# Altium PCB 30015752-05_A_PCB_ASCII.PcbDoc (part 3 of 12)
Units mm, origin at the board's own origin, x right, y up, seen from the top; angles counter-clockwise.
Board outline 100.05 x 72 mm, 10 copper layers (Top, GND_2, Signal_3, Signal_4, PWR_5, GND_6, Signal_7, Signal_8, GND_9, Bottom), stack 1.493 mm thick; 577 components, 546 nets, 2389 pads, 1412 vias.
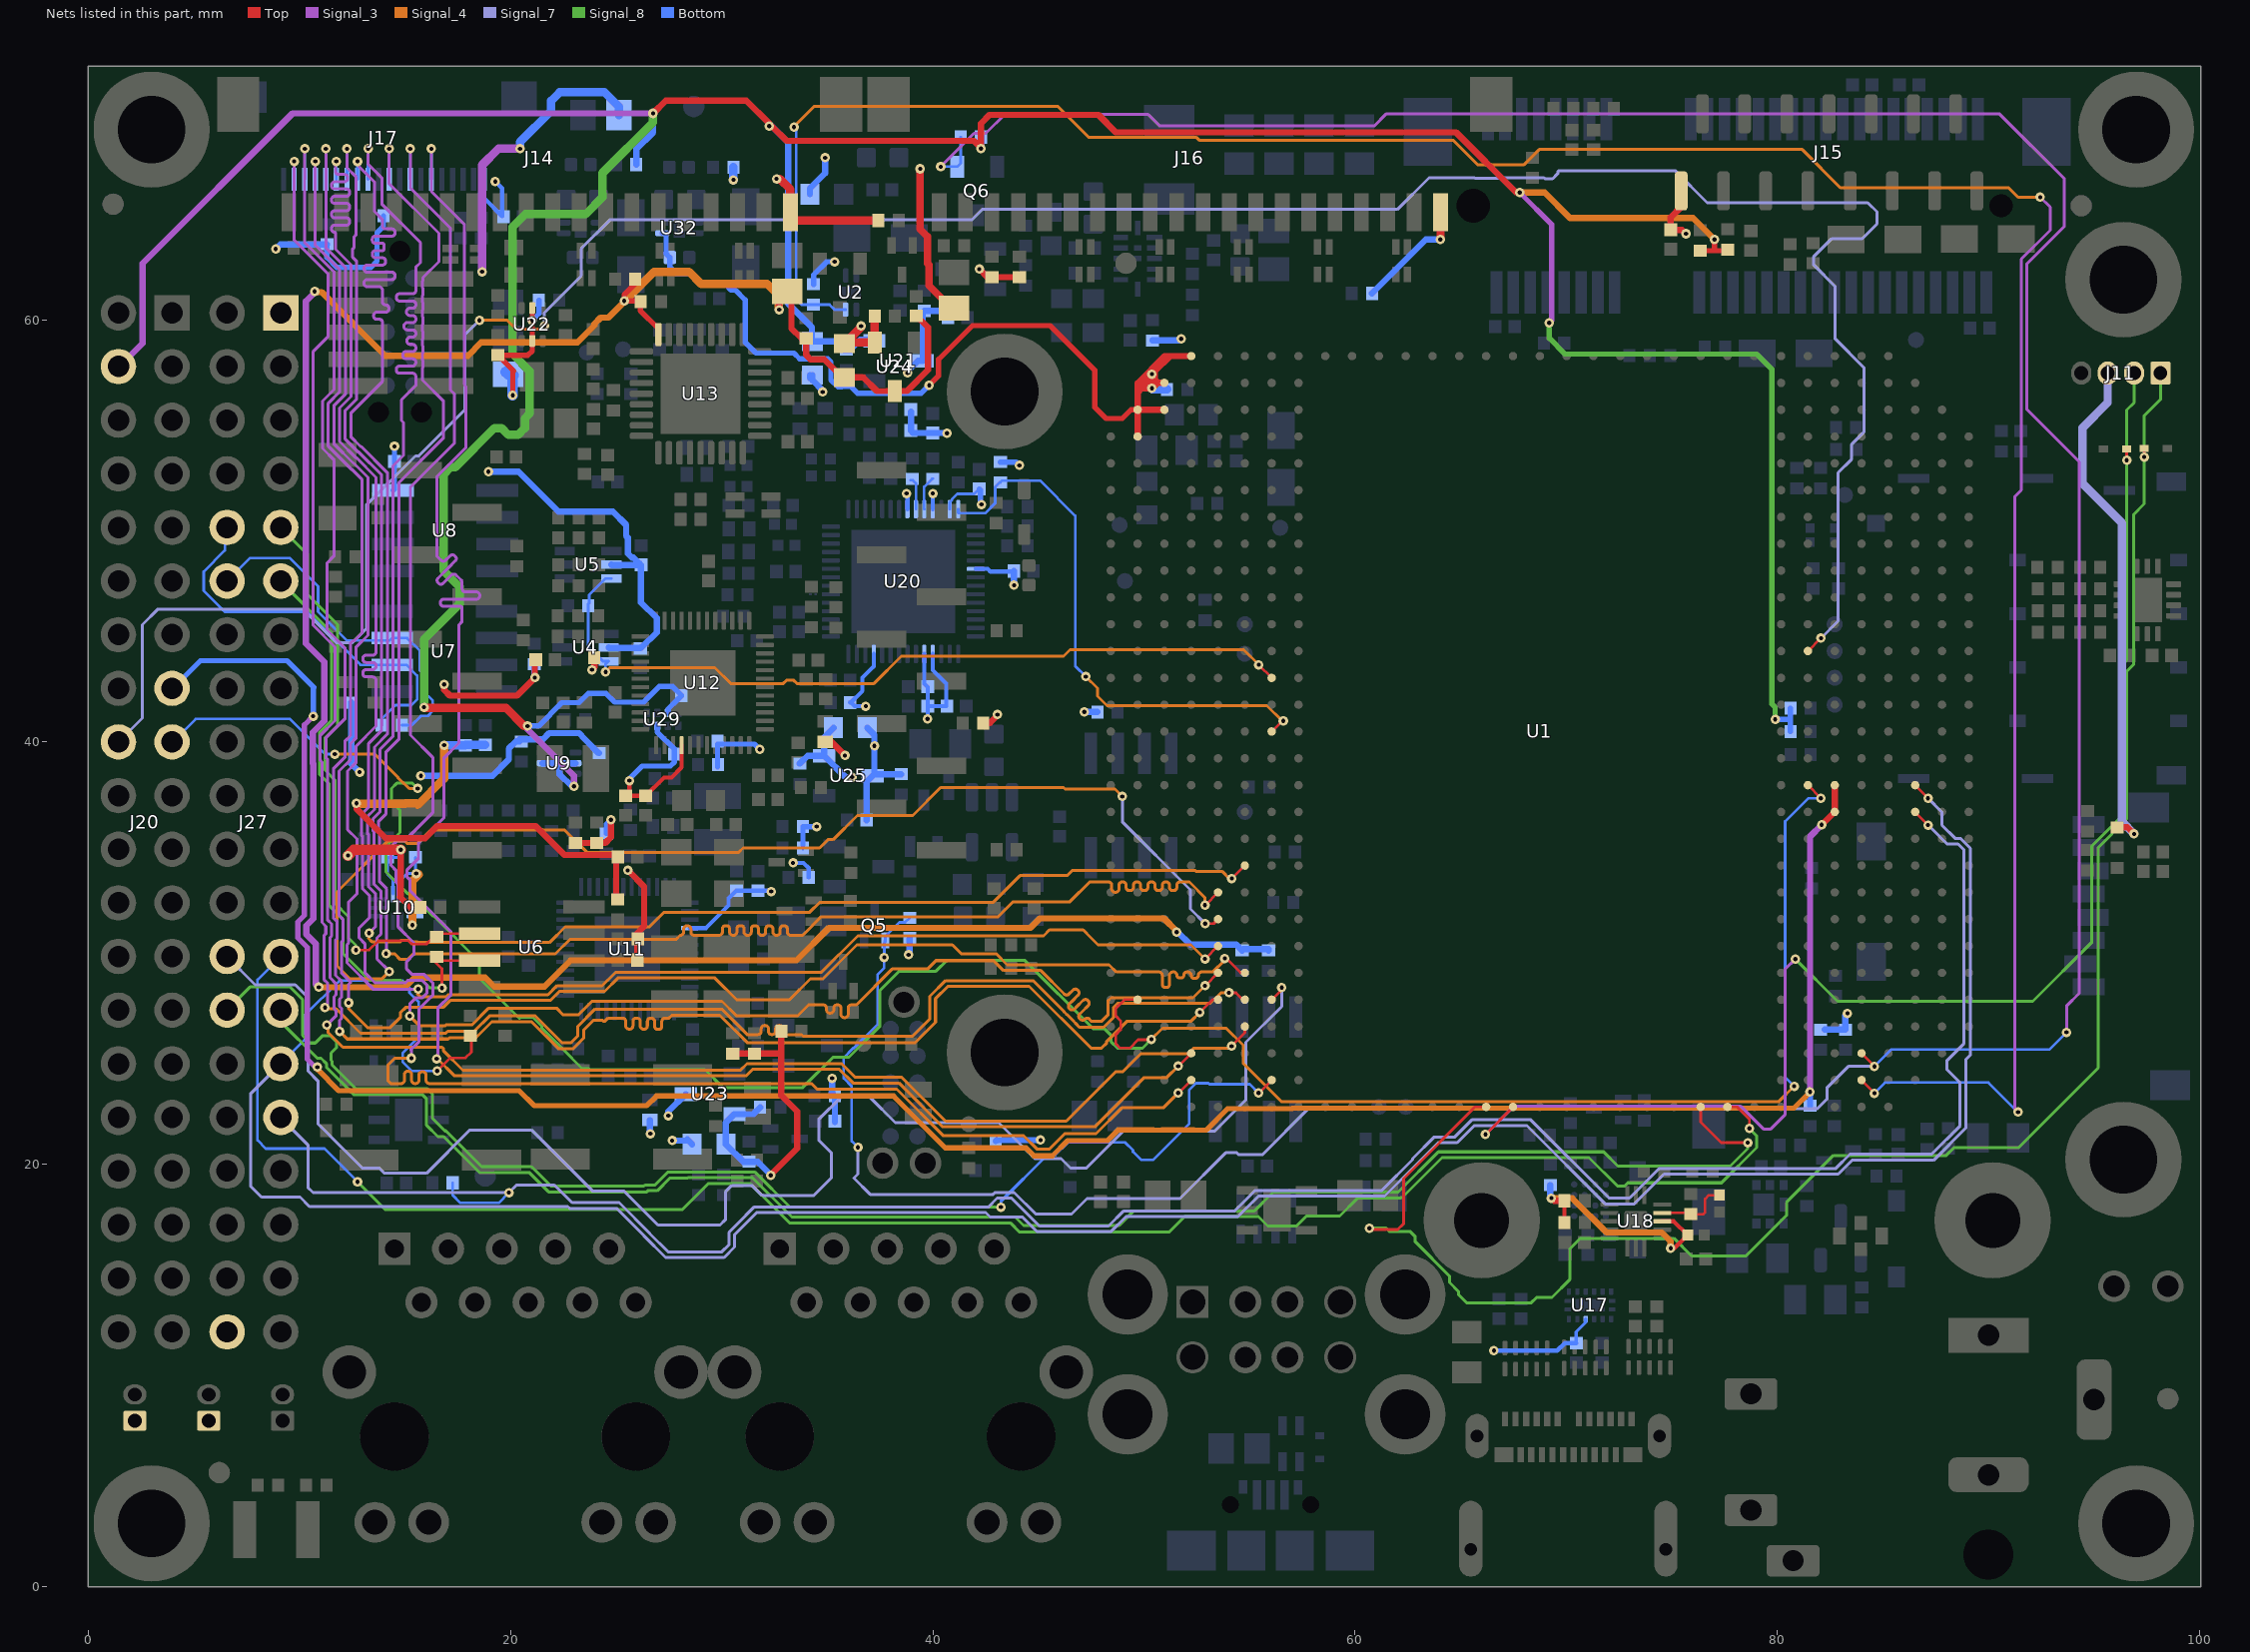
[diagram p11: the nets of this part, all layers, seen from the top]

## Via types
v1: diameter 0.45, hole 0.2, Top to Bottom, tented both sides, 1412 vias

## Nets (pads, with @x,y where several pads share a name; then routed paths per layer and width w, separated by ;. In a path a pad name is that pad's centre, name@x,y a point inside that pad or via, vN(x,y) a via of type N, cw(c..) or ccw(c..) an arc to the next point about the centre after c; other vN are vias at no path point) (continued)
1V8_CODEC: C120.2 C121.1 C122.1 C123.1 C133.2 R167.2 R199.2 U20.25 U20.50 U20.53 U21.D | length 13.7
  Bottom w0.2: C123.1@36.085,41.875 C123.1@36.125,41.875 ; v1(36.825,41.7) 36.3,41.7 C123.1@36.125,41.875 ; U20.25@37.2,44.17 37.2,43.586 36.668,43.054 36.668,42.418 C123.1@36.125,41.875 ; v1(38.75,51.775) 38.8,51.725 U20.50@38.8,51.03 ; U20.53@40,51.03 v1(40,51.775)
  Bottom w0.3: R199.2@34.175,57.375 34.175,57.25 R199.2@34.3,57.125 ; R199.2@34.3,57.375 R199.2@34.3,57.125 ; v1(34.777,56.578) 34.777,56.648 R199.2@34.3,57.125 ; v1(38.802,57.478) 38.802,57.552 39.3,58.05 U21.D@39.525,58.05 ; C120.2@38.96,55.65 C122.1@38.96,54.75 39.07,54.64 C121.1@40,54.64 40.66,54.64 v1(40.675,54.625) ; U21.D@39.55,58.075 39.525,58.1 39.525,60.345 R167.2@39.6,60.42 40.395,60.42 C133.2@40.715,60.1
1V8_EXT: C40.2 C44.2 J20.4 R3.1 R5.1 R6.1 R74.2 R106.2 R183.2 R184.2 R193.1 R194.1 R199.1 R244.1 U9.2 U9.5 U10.7 U10.10 U21.S U29.3 | length 212.7
  Top w0.25: R183.2@76.35,63.27 77.025,63.27 ; v1(77.025,63.8) 77.025,63.27 ; R184.2@77.5,63.27 77.025,63.27
  Top w0.3: v1(26.75,69.775) 27.358,70.383 31.166,70.383 32.25,69.299 v1(32.25,69.175) 32.375,69.175 33.075,68.475 41.944,68.475 v1@42.277,68.142 ; v1(42.277,68.103) v1@42.277,68.142 ; v1@67.602,66.058 64.783,68.877 48.673,68.877 47.848,69.702 42.682,69.702 42.277,69.297 v1@42.277,68.142
  Top w0.4: v1(15.9,41.65) 15.929,41.621 19.779,41.621 20.64,40.76 v1(20.8,40.76)
  Signal_3 w0.254: v1(67.8,66.025) 69.317,64.508 69.317,59.967 v1(69.2,59.85)
  Signal_3 w0.3: J20.4@1.46,57.78 2.56,58.88 2.56,62.66 9.675,69.775 v1(26.75,69.775) ; v1(20.8,40.76) 20.8,40.6 23,38.4 v1(23,37.9)
  Signal_8 w0.254: v1(69.2,59.85) 69.2,59.124 69.949,58.375 79.025,58.375 79.75,57.65 79.75,41.8 79.9,41.65 v1(79.9,41.075)
  Signal_8 w0.4: v1(15.9,41.65) 15.9,44.86 17.58,46.54 17.58,47.36 16.828,48.112 16.828,52.689 17.151,53.012 17.373,53.012 19.233,54.871 19.573,54.871 19.896,54.548 20.354,54.548 20.677,54.871 20.677,55.329 20.9,55.552 20.9,57.575 20.1,58.375 20.1,64.4 20.7,65 23.55,65 24.35,65.8 24.35,66.95 26.75,69.35 v1(26.75,69.775)
  Signal_4 w0.3: v1(67.8,66.025) 68.975,66.025 70.175,64.825 76,64.825 v1(77.025,63.8)
  Signal_4 w0.4: v1(15.351,31.327) 15.351,33.426 15.651,33.726 15.6,33.777 v1(15.526,33.777)
  Bottom w0.15: U10.7@14.825,32.8 14.825,33.5 15.102,33.777 v1(15.526,33.777) 15.5,33.802 C40.2@15.5,34.54 ; v1(15.351,31.327) 15.351,31.626 ; U10.10@15.35,31.75 U10.10@15.475,31.75
  Bottom w0.2: v1(33.377,34.277) 33.876,34.277 34.12,34.033 R74.2@34.12,33.592
  Bottom w0.254: v1(20.8,40.76) 21.326,40.76 22.434,41.868 23.239,41.868 23.675,42.304 24.513,42.304 24.929,41.888 26.296,41.888 27.037,42.629 27.671,42.629 28.09,42.21 C44.2@28.09,42.2 28.09,42.19 27.917,42.017 27.905,42.017 27.473,41.585 27.473,41.398 U29.3@27.45,41.375 ; R106.2@29.805,38.825 29.805,39.9 31.55,39.9 v1(31.8,39.65) ; v1(79.9,41.075) 80.62,41.075 ; R5.1@80.62,40.5 80.62,41.075 ; R6.1@80.62,41.6 80.62,41.075
  Bottom w0.3: U9.5@21.52,39 22.325,39 ; v1(23,37.9) 22.905,37.9 22.325,38.48 22.325,39 ; U9.2@23.08,39 22.325,39 ; R3.1@25.955,67.35 25.955,68.08 26.75,68.875 v1(26.75,69.775) ; v1(32.25,69.175) 32.375,69.175 33.15,68.4 33.15,60.764 34.275,59.639 34.275,59.075 34.175,58.975 R199.1@34.3,58.975 35.4,58.975 35.795,58.58 R193.1@35.9,58.58 36.088,58.58 36.558,59.05 U21.S@37.225,59.05 ; v1(42.277,68.103) 42.277,68.647 R194.1@42.28,68.65
3V3: C154.2 R256.2 U1.AK1 U1.AL2 U1.AL3 U1.AM3 U1.AM4 U32.3 | length 47.1
  Top w0.25: v1(39.825,56.9) 40.275,57.35 40.275,58.125 41.875,59.725 45.55,59.725 47.675,57.6 47.675,55.85 48.2,55.325 48.975,55.325 49.39,55.74 U1.AM3@49.7,55.74
  Top w0.3: U1.AM4@49.7,54.47 U1.AM3@49.7,55.74 ; U1.AL3@50.97,55.74 U1.AM3@49.7,55.74 ; U1.AL2@50.97,57.01 50.675,57.01 ; U1.AK1@52.24,58.28 51.23,58.28 ; U1.AM3@49.7,55.74 49.7,56.55 ; 49.7,56.55 49.9,56.75 v1(50.375,56.75) ; 49.7,56.55 49.7,56.75 ; 49.7,56.75 49.96,57.01 ; 49.7,56.75 49.7,57 50.98,58.28 51.23,58.28 ; 49.96,57.01 50.375,57.01 ; 49.96,57.01 v1(50.375,57.425) ; v1(50.375,56.75) 50.415,56.75 50.675,57.01 ; v1(50.375,56.75) 50.375,57 ; 50.375,57 50.385,57.01 ; 50.375,57 50.375,57.01 ; 50.375,57.01 50.385,57.01 ; 50.375,57.01 v1@50.375,57.31 ; v1@50.375,57.31 50.505,57.18 ; v1@50.375,57.31 v1(50.375,57.425) ; v1(50.375,57.425) v1@50.505,57.555 ; 50.385,57.01 50.675,57.01 ; 50.505,57.18 v1@50.505,57.555 ; 50.505,57.18 50.675,57.01 ; v1@50.505,57.555 51.23,58.28
  Bottom w0.25: U32.3@27.19,64.1 27.355,64.1 27.365,64.09 27.365,63.125 C154.2@27.54,62.95 27.54,62.51 27.85,62.2 28.575,62.2 29.125,61.65 30.201,61.65 30.449,61.402 30.648,61.402 31.111,60.939 31.111,60.646 31.111,58.939 31.628,58.422 33.422,58.422 33.694,58.15 35.025,58.15 35.175,58 35.175,57.15 35.498,56.827 35.676,56.827 35.704,56.855 36.099,56.855 36.379,56.575 36.379,56.571 36.427,56.523 39.448,56.523 v1(39.825,56.9)
  Bottom w0.4: v1(50.375,57.425) v1(50.375,56.75) 50.425,56.7 R256.2@51.095,56.7
3V3_CODEC: C118.1 C119.1 C124.2 C125.1 C126.1 C134.2 R166.2 R170.2 U20.6 U20.18 U20.19 U20.55 U25.D | length 18
  Bottom w0.127: U20.55@40.8,51.03 40.8,51.36 40.909,51.469 40.909,51.51 41.153,51.754 41.964,51.754 C119.1@42.2,51.99
  Bottom w0.2: U20.19@39.6,44.17 39.6,42.76 39.76,42.6 C125.1@39.76,41.7 ; v1(39.75,41.1) 39.76,41.11 C125.1@39.76,41.7 ; U20.18@40,44.17 40,43.4 40.64,42.76 40.64,41.7 C125.1@39.76,41.7 ; U20.6@42.03,48.2 42.6,48.2 42.725,48.075 43.815,48.075 C118.1@43.84,48.1
  Bottom w0.25: C119.1@42.2,51.99 42.25,51.94 42.25,51.3 v1(42.3,51.25)
  Bottom w0.3: C134.2@36.86,36.3 36.86,38.11 U25.D@37.15,38.4 37.23,38.48 U25.D@37.232,38.48 ; R170.2@36.9,40.675 37.232,40.343 v1(37.232,39.825) U25.D@37.232,38.48 ; R166.2@38.5,38.48 U25.D@37.232,38.48 ; C118.1@43.84,48.1 43.84,47.435 v1(43.85,47.425)
3V3_ETH: C41.2 C47.2 C48.2 C62.2 C65.2 C66.2 L2.1 L5.1 R71.2 R72.2 R73.2 R75.2 R104.2 R105.2 R107.2 R160.2 U11.4 U12.4 U23.D U29.7 | length 26.3
  Top w0.2: v1(25.625,38.175) 25.625,37.485 25.6,37.46 C65.2@26.4,37.46 26.41,37.46 27.272,38.322 27.622,38.322 28.1,38.8 U12.4@28.1,39.85
  Top w0.3: R105.2@23.075,35.22 R104.2@24.075,35.22 24.48,35.22 24.75,35.49 v1(24.75,36.325) ; v1(23.85,43.425) 23.97,43.545 R107.2@23.97,44 ; L5.1@34.9,40.02 35.18,40.02 v1(35.84,39.36)
  Bottom w0.2: U11.4@28.49,31.192 29.262,31.192 30.327,32.257 30.327,32.592 C48.2@30.7,32.965 C47.2@31.725,32.965 32.295,32.965 v1(32.34,32.92)
  Bottom w0.254: R75.2@24.54,35.672 24.54,36.115 v1(24.75,36.325) ; v1(25.625,38.175) 25.625,38.252 26.234,38.861 27.569,38.861 27.76,39.052 C62.2@27.76,39.425 27.76,39.665 26.95,40.475 U29.7@26.95,40.775 ; R72.2@33.845,34.992 R73.2@33.845,35.992 34.492,35.992 v1(34.5,36)
  Bottom w0.3: L2.1@26.6,22.095 26.6,21.475 v1(26.625,21.45) ; v1(27.476,22.301) 27.476,22.501 U23.D@28.3,23.325 ; v1(27.651,21.126) 28.326,21.126 28.375,21.175 R71.2@28.6,20.95 ; v1(35.227,24.076) 35.227,23.432 35.2,23.405 R160.2@35.355,23.25 35.36,23.245 C41.2@35.36,22.05 C41.2@35.36,22
3V3_EXT: C29.1 C30.1 C31.2 C32.2 C33.2 C39.2 C78.2 C80.2 C98.2 C101.2 J2.1 J11.3 J14.1 J15.1 J16.1 J17.20 J27.1 L22.1 R2.1 R16.1 R29.1 R40.1 R42.2 R46.1 R57.2 R69.1 R70.1 R71.1 R80.1 R144.1 R145.1 R146.1 R147.1 R148.1 R149.1 R154.1 R168.1 R169.1 R170.1 R171.2 R172.2 R179.2 R180.2 R181.2 R182.2 R196.2 R203.2 R204.2 R235.2 R246.1 R247.2 R249.1 R250.2 R251.1 R253.1 R257.1 U4.5 U5.5 U8.8 U10.6 U17.4 U18.3 U22.2 U22.5 U23.S U24.S U25.S | length 166.6
  Top w0.2: R148.1@69.92,17.25 R147.1@69.92,18.275 ; U18.3@74.55,17.3 75.1,17.3 C101.2@75.75,16.65 75.125,16.025 v1(74.95,16.025)
  Top w0.25: v1(20.101,56.428) 20.101,57.521 20.15,57.57 R251.1@19.4,58.32 20.82,58.32 21.025,58.525 U22.2@21.025,58.995 v1(21.025,59.975) U22.5@21.025,60.555
  Top w0.3: v1(14.8,34.9) 14.8,32.675 14.775,32.65 15.25,32.175 R247.2@15.72,32.175 ; v1(16.85,42.725) 16.85,42.475 17.127,42.198 20.298,42.198 v1(21.15,43.05) 21.15,43.86 C32.2@21.19,43.9 ; v1(25.55,33.925) 26.325,33.15 26.325,31.275 26.005,30.955 26.005,30.9 26.01,30.895 C31.2@26.01,29.675 ; R204.2@30.525,25.245 R203.2@31.55,25.245 32.765,25.245 32.82,25.3 ; v1(32.327,19.476) 32.327,19.502 33.577,20.752 33.577,22.503 32.82,23.26 32.82,25.3 ; R42.2@32.82,26.3 32.82,25.3 ; v1(42.2,62.4) 42.58,62.02 R181.2@42.8,62.02 R182.2@44.1,62.02 ; R196.2@42.38,40.9 42.7,40.9 43.06,41.26 v1(43.06,41.3) ; v1(69.3,18.4) 69.425,18.275 R147.1@69.92,18.275 ; J15.1@75.45,66.1 75.45,65.35 74.95,64.85 C78.2@74.95,64.26 75.49,64.26 v1(75.675,64.075) ; R57.2@96.1,35.96 96.59,35.96 v1(96.9,35.65)
  Top w0.4: v1(32.6,66.675) 32.75,66.675 33.25,66.175 J14.1@33.25,65.1 33.25,64.7 R144.1@37.42,64.7 ; R146.1@35.809,58.869 R146.1@35.865,58.925 ; v1(36.6,59.7) 36.6,59.66 R146.1@35.865,58.925 ; R145.1@37.245,60.175 37.25,60.17 U24.S@37.25,58.925 R146.1@35.865,58.925 ; v1(64.04,63.8) 64.05,63.81 J16.1@64.05,65.1
  Top w0.5: v1(12.3,34.625) 12.575,34.9 v1(14.8,34.9)
  Signal_4 w0.3: v1(69.3,18.4) 70.275,18.4 71.9,16.775 74.525,16.775 74.95,16.35 v1(74.95,16.025)
  Signal_7 w0.4: J11.3@95.65,57.475 95.65,56.075 94.463,54.888 94.463,52.237 96.325,50.375 96.325,43.631 96.327,43.629 96.327,43.171 96.325,43.169 96.325,42.031 96.327,42.029 96.327,41.571 96.325,41.569 96.325,37.131 96.327,37.129 96.327,36.671 96.325,36.669 96.325,36.225 v1(96.9,35.65)
  Bottom w0.15: U10.6@14.425,32.8 14.425,33.5 14.175,33.75 C39.2@14.175,34.54 14.69,34.54 14.8,34.65 v1(14.8,34.9) ; C98.2@70.475,11.535 70.475,12.064 70.925,12.514 U17.4@70.925,12.675
  Bottom w0.2: J17.20@18.75,66.65 18.75,65.75 19.6,64.9 19.6,66.225 v1(19.275,66.55) ; v1(66.575,11.175) 69.575,11.175 69.935,11.535 C98.2@70.475,11.535
  Bottom w0.25: R179.2@11.3,63.57 11.3,62.95 11.775,62.475 13.375,62.475 13.675,62.775 13.675,64.125 13.98,64.43 R180.2@13.98,64.925 ; v1(21.025,59.975) 21.345,60.295 R253.1@21.345,60.925 ; R40.1@34.35,61.68 34.35,62.125 34.975,62.75 v1(35.35,62.75) ; R154.1@43.2,53.26 43.945,53.26 v1(44.102,53.103)
  Bottom w0.254: U8.8@14.43,51.915 14.499,51.984 C33.2@14.499,53.281 v1@14.499,53.999
  Bottom w0.3: v1(8.875,63.35) 9.095,63.57 10,63.57 R179.2@11.3,63.57 ; R250.2@12.45,41.87 12.45,38.975 v1(12.85,38.575) ; v1(15.75,38.4) 19.141,38.4 19.913,39.172 19.913,39.688 20.255,40.03 R16.1@20.425,40.03 ; v1(18.95,52.8) 20.37,52.8 22.264,50.906 24.851,50.906 25.473,50.284 25.473,49.767 25.552,49.688 25.552,48.931 25.75,48.733 25.822,48.733 26.093,48.462 26.093,48.39 24.785,48.39 U5.5@24.775,48.4 ; R16.1@20.425,40.123 21.531,40.123 21.835,40.427 23.233,40.427 23.527,40.133 23.527,40.123 24.17,39.48 R80.1@24.2,39.48 ; R249.1@21.125,43.695 21.125,43.075 v1(21.15,43.05) ; U4.5@24.65,44.475 24.67,44.455 26.155,44.455 26.175,44.475 26.2,44.475 26.922,45.197 26.922,45.868 26.175,46.615 C30.1@26.175,48.39 ; R70.1@31.82,22.7 31.495,22.375 U23.S@30.6,22.375 30.2,21.975 R71.1@30.2,20.95 31.03,20.12 R69.1@31.3,20.12 31.705,20.12 32.327,19.498 v1(32.327,19.476) ; R169.1@33.7,38.98 34.07,39.35 U25.S@34.85,39.35 ; R170.1@35.3,40.675 34.85,40.225 U25.S@34.85,39.35 ; v1(36.18,38.34) 35.86,38.34 U25.S@34.85,39.35 ; v1(38.852,29.926) 38.874,29.926 38.9,29.9 R168.1@38.9,30.72 ; R29.1@42.98,21.1 43.031,21.151 43.032,21.15 v1(45.1,21.15) ; v1(47.175,41.425) R235.2@47.795,41.425 ; R46.1@50.4,59.02 51.68,59.02 v1(51.76,59.1) ; R257.1@60.805,61.25 63.355,63.8 v1(64.04,63.8) ; R149.1@69.25,19.02 69.25,18.45 v1(69.3,18.4) ; R171.2@82.25,26.38 R172.2@83.225,26.38 83.225,27.05 v1(83.325,27.15)
  Bottom w0.4: v1(30.555,66.625) R2.1@30.555,67.225
  Bottom w0.5: L22.1@19.875,57.425 19.775,57.525 20,57.525 20.15,57.375 20.101,57.326 v1(20.101,56.428)
  other v1: 14.5,54
3V3_RF: J20.15 R10.2 U1.F17 U1.F18 | length 116.3
  Top w0.3: v1(82.1,36.08) 82.11,36.08 U1.F18@82.72,36.69 U1.F17@82.72,37.96
  Signal_3 w0.25: v1(10.651,41.227) 10.233,40.81 10.233,31.787 9.921,31.474 9.921,30.726 10.371,30.276 10.371,24.979 10.749,24.601 v1(10.851,24.601)
  Signal_3 w0.3: v1(81.55,23.425) 81.55,35.53 v1(82.1,36.08)
  Signal_4 w0.25: v1(10.851,24.601) 10.851,24.499 11.856,23.494 20.4,23.494 21.12,22.774 26.449,22.774 26.912,23.237 38.138,23.237 40.6,20.775 44.42,20.775 44.791,20.404 45.425,20.404 45.664,20.404 46.385,21.125 48.275,21.125 48.777,21.627 50.448,21.627 50.452,21.623 50.848,21.623 50.852,21.627 52.348,21.627 52.352,21.623 52.954,21.623 53.965,22.634 57.009,22.634 57.032,22.657 58.44,22.657 80.782,22.657 v1(81.55,23.425)
  Bottom w0.25: J20.15@4,42.54 5.31,43.85 9.419,43.85 10.675,42.594 10.651,42.57 v1(10.651,41.227)
  Bottom w0.3: R10.2@81.55,22.78 v1(81.55,23.425)
3V3_USB: C89.2 L15.2 R136.2 R137.2 R142.2 R143.2 R146.2 R161.2 U13.27 U24.D | length 125.9
  Top w0.25: R136.2@25.905,61.925 25.905,61.705 25.383,61.183 v1(25.383,60.898) 25.972,60.898 R137.2@26.07,60.8 ; R137.2@26.13,60.79 26.145,60.775 26.145,60.43 27,59.575 U13.27@27,59.3
  Top w0.3: v1(32.727,60.478) 32.727,60.923 32.7,60.95 L15.2@33.1,61.35 33.3,61.35 33.3,59.6 33.78,59.12 R161.2@34,59.12 34,58.325 34.205,58.12 34.855,58.12 35.706,57.269 R146.2@35.809,57.269 36.706,57.269 37.35,56.625 U24.D@38.2,56.625 38.775,56.625 39.773,57.623 39.773,59.642 C89.2@39.225,60.19
  Signal_3 w0.3: v1(10.72,61.34) 10.72,61.295 10.304,60.879 10.304,44.671 11.177,43.798 11.177,40.998 10.635,40.457 10.635,38.996 10.652,38.979 10.652,31.637 10.323,31.308 10.323,30.892 10.773,30.442 10.773,28.527 v1(10.913,28.387)
  Signal_4 w0.3: v1(10.72,61.34) 10.749,61.311 11.05,61.311 14.063,58.298 17.981,58.298 18.612,58.929 23.167,58.929 23.973,59.734 23.973,59.808 24.267,60.102 24.627,60.102 25.383,60.858 v1(25.383,60.898) ; v1(10.913,28.387) 14.987,28.387 15.453,28.853 18.797,28.853 19.225,28.425 21.6,28.425 22.834,29.659 33.537,29.659 35.078,31.2 44.625,31.2 45.075,31.65 50.95,31.65 51.553,31.047 v1(51.553,31.002)
  Signal_4 w0.4: v1(25.383,60.898) 25.423,60.898 26.8,62.275 28.45,62.275 29.025,61.7 30.294,61.7 30.299,61.705 32.145,61.705 32.706,61.144 32.706,60.497 v1(32.727,60.478) v1(32.727,60.478)
  Bottom w0.3: v1(51.553,31.002) 51.598,31.002 52.2,30.4 54.38,30.4 R142.2@54.65,30.13 54.722,30.202 55.9,30.202 R143.2@55.9,30.13
5V: C145.2 C146.2 J3.1 J27.40 L8.1 L36.1 R41.2 R245.1 R248.1 | length 47.9
  Top w0.3: v1(12.701,37.102) 12.701,36.839 14.09,35.45 15.95,35.45 16.525,36.025 21.175,36.025 22.548,34.652 25.09,34.652 C145.2@25.09,34.55 25,34.46 25,32.63 R245.1@25.075,32.555
  Top w0.35: v1(39.4,67.15) 39.4,64.288 39.752,63.936 39.752,62.669 39.812,62.609 39.812,61.613 40.875,60.55 L36.1@41,60.55
  Signal_3 w0.4: v1(18.65,62.275) 18.65,67.325 19.425,68.1 v1(20.45,68.1)
  Signal_4 w0.4: v1(12.701,37.102) 12.734,37.068 15.009,37.068 15.042,37.102 15.529,37.102 15.606,37.025 16.85,38.269 v1(16.85,39.85)
  Bottom w0.3: R41.2@34.175,65.95 34.175,66.215 34.9,66.94 v1(34.9,67.675)
  Bottom w0.4: v1(16.85,39.85) 17.695,39.85 R248.1@17.7,39.845 ; R248.1@17.75,39.845 R248.1@17.85,39.845 17.87,39.865 C146.2@18.8,39.865 ; v1(20.45,68.1) 20.45,68.425 21.925,69.9 21.925,70.375 22.325,70.775 24.45,70.775 25.125,70.1 L8.1@25.125,69.7
5V_SBC_PWR_ON: R40.2 U1.E28 U2.4 | length 125.6
  Top w0.127: U1.E28@83.99,23.99 84.6,23.38 v1(84.6,23.37)
  Signal_3 w0.142: v1(91.4,22.475) 91.257,22.618 91.257,51.632 91.558,51.933 91.558,62.875 92.925,64.242 92.925,65.335 92.457,65.803 v1(92.455,65.803)
  Signal_4 w0.142: v1(33.427,69.128) 33.427,69.152 34.379,70.104 41.689,70.104 45.921,70.104 47.374,68.651 52.47,68.651 52.617,68.504 64.64,68.504 65.797,67.346 68.012,67.346 68.727,68.062 81.182,68.062 82.989,66.255 90.954,66.255 91.406,65.803 v1(92.455,65.803)
  Bottom w0.127: v1(33.427,69.128) 33.427,69.152 33.534,69.259 33.534,60.966 33.78,60.72 R40.2@34.35,60.72 35.11,60.72 35.35,60.48 U2.4@35.875,60.48 ; v1(84.6,23.37) 85.102,23.872 90.003,23.872 v1(91.4,22.475)
ADC_IN0: J27.25 U1.K29 | length 88.9
  Top w0.127: U1.K29@77.64,22.72 78.105,22.72 78.679,22.146 v1(78.679,21.701)
  Signal_8 w0.142: v1(12.75,19.175) 14.073,17.852 28.126,17.852 29.375,19.101 31.341,19.101 33.211,17.231 43.669,17.231 44.1,16.8 51.2,16.8 51.925,17.525 55.422,17.525 55.863,17.083 57.233,17.083 57.7,17.55 59.275,17.55 60.139,18.414 62.151,18.414 62.162,18.425 62.225,18.425 64.122,20.322 71.079,20.322 72.425,18.977 72.775,18.977 72.923,19.125 77.356,19.125 79.023,20.792 79.023,21.352 78.679,21.696 v1(78.679,21.701)
  Bottom w0.127: J27.25@9.1,29.84 8.009,28.749 8.009,21.141 8.405,20.745 11.18,20.745 v1(12.75,19.175)
ADC_IN1: J27.27 U1.L29 | length 81.1
  Top w0.127: U1.L29@76.37,22.72 76.37,22.005 77.35,21.025 v1(78.6,21.025)
  Signal_8 w0.142: J27.27@9.1,27.3 9.1,26.769 10.845,25.024 11.026,25.024 11.274,24.776 11.274,24.601 12.569,23.306 15.819,23.306 16.025,23.1 16.025,21.85 16.559,21.315 16.825,21.315 18.521,19.619 20.879,19.619 21.8,18.698 26.45,18.698 26.502,18.75 26.946,18.75 27.553,19.357 28.384,19.357 28.398,19.37 31.452,19.37 33.323,17.5 43.9,17.5 44.298,17.102 48.829,17.102 49.521,17.794 55.24,17.794 56.129,18.684 62.039,18.684 63.947,20.591 71.776,20.591 72.446,19.921 77.771,19.921 78.6,20.75 v1(78.6,21.025)
ADC_IN4: J27.26 U1.AG25 | length 74.2
  Top w0.127: U1.AG25@56.05,27.8 56.525,28.275 v1(56.525,28.375)
  Signal_7 w0.142: J27.26@6.56,29.84 7.9,28.5 9.8,28.5 10.404,27.896 10.404,24.421 10.875,23.95 10.875,21.925 12.985,19.815 13.79,19.815 14.031,19.575 16.025,19.575 18.077,21.627 19.117,21.627 19.12,21.63 20.991,21.63 23.876,18.744 25.36,18.744 26.977,17.127 29.925,17.127 30.173,17.375 30.173,18.698 30.481,19.006 31.428,19.006 31.9,18.534 31.963,18.534 31.97,18.528 34.372,18.528 35.2,19.356 35.2,20.548 34.598,21.15 34.598,22.132 35.664,23.198 37,23.198 38.221,21.977 43.123,21.977 44.825,20.275 46.071,20.275 46.521,19.825 47.275,19.825 49.025,21.575 53.35,21.575 54.825,23.05 54.825,25.778 56.525,27.478 v1(56.525,28.375)
ADC_IN5: J27.28 U1.AG28 | length 62.4
  Top w0.127: v1(55.43,23.38) 55.44,23.38 U1.AG28@56.05,23.99
  Signal_8 w0.142: J27.28@6.56,27.3 7.658,28.398 9.555,28.398 10.151,27.802 10.151,26.104 10.508,25.747 10.748,25.747 11.1,26.099 11.451,26.099 11.749,25.802 11.749,25.522 11.501,25.274 11.501,24.93 11.543,24.888 11.543,24.713 12.681,23.575 16.05,23.575 16.294,23.331 16.294,22.179 16.888,21.585 16.936,21.585 18.632,19.888 20.99,19.888 21.911,18.967 26.313,18.967 26.365,19.019 26.835,19.019 27.442,19.626 28.273,19.626 28.286,19.64 31.564,19.64 33.228,17.976 v1(43.227,17.976)
  Bottom w0.127: v1(43.227,17.976) 43.227,18.248 43.225,18.25 45.405,20.431 45.79,20.431 46.4,21.041 49.109,21.041 49.483,20.667 49.483,20.599 49.875,20.207 50.43,20.207 52.134,21.911 52.134,23.509 52.467,23.842 53.05,23.842 53.096,23.795 55.015,23.795 v1(55.43,23.38)
AUD_I2C_SCL: R175.2 U20.51 | length 1.5
  Bottom w0.127: R175.2@38.95,52.4 39.049,52.4 39.2,52.249 U20.51@39.2,51.03
AUD_I2C_SDA: R176.2 U20.52 | length 1.6
  Bottom w0.127: U20.52@39.6,51.03 39.584,51.046 39.584,52.08 39.975,52.47 R176.2@40,52.47
AUD_INT#: R154.2 U1.AG15 U20.56 | length 26.5
  Top w0.127: U1.AG15@56.05,40.5 56.55,41 v1(56.6,41)
  Signal_4 w0.142: v1(47.25,43.1) 47.8,42.55 47.8,42.175 48.25,41.725 55.825,41.725 56.55,41 v1(56.6,41)
  Bottom w0.127: U20.56@41.2,51.03 41.2,50.871 41.236,50.834 42.472,50.834 42.954,51.316 42.954,52.078 43.175,52.3 R154.2@43.2,52.3 43.286,52.386 45.081,52.386 46.746,50.72 46.746,43.604 v1(47.25,43.1)
AUD_PWR_EN: Q5.G Q6.G R168.2 R194.2 U1.E27 | length 178
  Top w0.127: U1.E27@83.99,25.26 84.6,24.65 v1(84.6,24.64)
  Signal_3 w0.142: v1(40.375,67.25) 41.95,68.825 42.507,68.825 43.411,69.729 50.2,69.729 50.754,69.175 60.9,69.175 61.466,69.741 90.534,69.741 93.6,66.675 93.6,64.425 91.827,62.652 91.827,55.752 94.298,53.28 94.298,28.098 93.7,27.5 v1(93.7,26.25)
  Signal_7 w0.142: v1(36.45,20.8) 36.45,19.54 36.26,19.35 37.033,18.577 42.849,18.577 42.94,18.668 43.857,18.668 44.875,17.65 46.575,17.65 47.3,18.375 51.7,18.375 53.873,20.548 54.4,20.548 54.498,20.45 55.604,20.45 57.8,22.646 81.907,22.646 82.349,23.088 82.349,23.624 83.365,24.64 v1(84.6,24.64)
  Bottom w0.127: v1(36.45,20.8) 36.159,21.091 36.159,23.691 35.78,24.069 35.78,25.052 36.224,25.496 36.249,25.496 37.384,26.631 37.384,28.992 37.695,29.303 v1@37.695,29.85 ; v1(37.702,29.801) 37.702,30.492 37.76,30.55 37.725,30.585 Q5.G@37.75,30.61 37.75,30.795 38.413,31.459 38.679,31.459 R168.2@38.9,31.68 ; Q5.G@37.725,30.53 Q5.G@37.75,30.555 ; v1(40.375,67.25) Q6.G@41.15,67.25 41.32,67.42 R194.2@41.32,68.65 ; v1(84.6,24.64) 85.405,25.445 92.895,25.445 v1(93.7,26.25)
BT_WAKEUP_HOST: J20.17 U1.AM25 U1.G17 | length 119.5
  Top w0.127: U1.AM25@49.7,27.8 49.075,27.8 48.665,27.39 48.665,27.028 48.9,26.792 48.9,26.375 48.665,26.14 48.665,25.71 48.871,25.504 49.329,25.504 49.725,25.9 v1@50.3,25.9 ; v1(50.35,25.92) v1@50.36,25.92 ; U1.G17@81.45,37.96 82.06,37.35 v1(82.06,37.34)
  Signal_8 w0.142: v1(15.6,37.8) 15.35,38.05 14.612,38.05 14.357,37.795 14.357,37.178 14.76,36.775 14.76,35.714 14.096,35.05 14.096,33.846 15.127,32.815 15.271,32.815 15.425,32.662 15.425,32.654 16.304,31.775 16.34,31.775 18.52,29.594 18.52,28.813 20.418,26.915 20.436,26.915 20.488,26.967 21.062,26.967 21.467,26.562 21.467,26.452 22.435,25.485 22.443,25.485 23.396,24.531 23.71,24.531 23.757,24.484 29.208,24.484 30.054,23.638 33.838,23.638 35.275,25.075 36.025,25.075 37.5,26.55 37.5,28.24 38.408,29.148 40.148,29.148 40.656,29.656 44.365,29.656 47.59,26.431 48.119,26.431 48.45,26.1 48.45,25.797 48.75,25.497 49.927,25.497 v1(50.35,25.92)
  Signal_4 w0.142: v1(11.676,39.427) 13.571,39.427 14.677,38.322 14.677,38.3 14.925,38.052 14.947,38.052 15.198,37.8 v1(15.6,37.8) ; v1(50.35,25.92) 50.88,26.45 53.898,26.45 54.708,25.641 54.708,24.774 56.525,22.957 56.875,22.957 56.898,22.98 58.306,22.98 80.08,22.98 v1(80.8,23.7)
  Bottom w0.127: J20.17@4,40 5.091,41.09 9.552,41.09 11.242,39.4 11.269,39.427 v1(11.676,39.427) ; v1(80.8,23.7) 80.375,24.126 80.375,36.242 81.472,37.34 v1(82.06,37.34)
BT_WAKEUP_SLAVE: J20.18 U1.G12 | length 131.3
  Top w0.127: U1.G12@81.45,44.31 82.06,44.92 v1(82.07,44.92)
  Signal_4 w0.142: v1(18.525,59.975) 19.85,59.975 20.273,59.552 21.452,59.552 v1(21.6,59.7)
  Signal_7 w0.142: J20.18@1.425,40.005 2.556,41.136 2.556,45.556 3.3,46.3 10.15,46.3 11.737,44.713 12.512,44.713 13.167,45.369 13.167,49.737 13.165,49.739 13.165,51.221 15.499,53.555 15.651,53.555 17.831,55.734 17.831,59.281 v1(18.525,59.975) ; v1(21.6,59.7) 21.6,60.329 23.35,62.079 23.35,63.375 24.701,64.726 41.844,64.726 42.343,65.225 62,65.225 63.504,66.729 65.65,66.729 65.679,66.7 66.921,66.7 66.95,66.729 68.953,66.729 69.005,66.677 69.355,66.677 69.603,66.925 69.603,66.998 69.666,67.062 75.16,67.062 76.678,65.544 84.274,65.544 84.3,65.517 84.312,65.517 84.717,65.112 84.717,64.538 84.01,63.831 82.562,63.831 81.724,62.993 81.724,62.591 82.725,61.591 82.725,59.115 84.1,57.74 84.1,54.675 83.525,54.1 83.525,53.4 82.881,52.756 82.881,45.731 v1(82.07,44.92)
BYPASS: C102.2 R234.2 U18.4 | length 3.5
  Top w0.127: U18.4@74.55,17.7 75.84,17.7 R234.2@75.9,17.64 76.5,17.64 76.58,17.72 76.58,18.36 76.76,18.54 C102.2@77.26,18.54
CAN1_H: J27.11 R60.2 U6.7 | length 28.6
  Top w0.127: v1(16.751,28.351) 16.751,29.269 16.35,29.67 R60.2@16.5,29.82 16.665,29.655 U6.7@18.53,29.655
  Signal_8 w0.142: J27.11@9.1,47.62 11.525,45.195 11.525,41.025 10.942,40.442 10.942,38.483 11.41,38.015 11.41,32.255 12.056,31.61 12.056,29.994 13.34,28.71 14.067,28.71 14.075,28.702 14.425,28.702 14.433,28.71 14.802,28.71 14.881,28.631 15.357,28.631 15.451,28.725 15.801,28.725 16.174,28.351 v1(16.751,28.351)
CAN1_L: J27.9 R60.1 U6.6 | length 28.3
  Top w0.127: v1(12.675,30.15) 13.3,30.15 13.742,30.592 15.173,30.592 15.333,30.432 16.019,30.432 16.368,30.78 R60.1@16.5,30.78 16.645,30.925 U6.6@18.53,30.925
  Signal_8 w0.142: J27.9@9.1,50.16 10.392,48.868 10.392,46.975 11.8,45.567 11.8,40.8 11.211,40.211 11.211,38.673 11.68,38.205 11.68,32.367 12.325,31.721 12.325,30.719 12.675,30.369 v1(12.675,30.15)
CAN1_MODE: J27.29 R11.1 U1.C17 | length 130.4
  Top w0.127: v1(16.52,24.42) 17.14,25.04 17.86,25.04 18.14,25.32 18.14,26.04 R11.1@18.1,26.08 ; U1.C17@86.53,37.96 87.14,37.35 v1(87.14,37.34)
  Signal_7 w0.142: J27.29@9.1,24.76 7.7,23.36 7.7,18.95 8.2,18.45 10.025,18.45 10.469,18.006 22.711,18.006 22.799,17.917 25.027,17.917 26.319,16.625 26.319,16.617 27.348,15.588 30.119,15.588 30.612,16.081 30.612,16.671 30.981,17.04 30.981,17.042 31.658,17.72 42.504,17.72 42.72,17.504 44.242,17.504 44.938,16.808 48.435,16.808 49.158,17.531 54.456,17.531 55.425,18.5 61.4,18.5 63.931,21.031 64.837,21.031 65.644,21.838 68.137,21.838 71.844,18.131 73.231,18.131 74.638,19.538 82.883,19.538 83.538,20.194 87.406,20.194 88.925,21.713 88.925,24.95 89.149,25.174 89.149,34.966 88.675,35.44 88.42,35.44 87.8,36.06 87.8,36.68 v1(87.14,37.34)
  Bottom w0.127: J27.29@9.1,24.76 10.25,25.91 10.25,27.058 11.892,28.7 14.875,28.7 15.21,28.365 15.21,28.129 15.64,27.699 15.64,26.016 14.885,25.26 14.885,24.854 15.319,24.42 v1(16.52,24.42)
CAN2_H: J27.12 R62.2 U7.7 | length 17.1
  Bottom w0.127: J27.12@6.56,47.62 7.651,48.71 9.552,48.71 10.882,47.38 10.882,46.18 12.253,44.809 14.273,44.809 U7.7@14.389,44.926 15.099,44.926 15.7,44.325 15.7,43.384 15.829,43.255 15.829,42.44 16.316,41.953 16.316,41.478 16.072,41.234 15.75,41.234 15.316,40.8 R62.2@14.855,40.8
CAN2_L: J27.10 R62.1 U7.6 | length 18.7
  Bottom w0.127: J27.10@6.56,50.16 6.467,50.067 6.467,49.07 5.469,48.072 5.469,47.168 6.467,46.17 10.381,46.17 12.896,43.656 U7.6@14.389,43.656 15.069,43.656 15.575,43.15 15.575,42.017 15.308,41.75 14.55,41.75 13.895,41.095 R62.1@13.895,40.8
CAN2_MODE: J27.31 R233.1 U1.C18 | length 111
  Top w0.127: U1.C18@86.53,36.69 87.14,36.08 v1(87.14,36.07)
  Signal_7 w0.142: J27.31@9.1,22.22 10.4,20.92 10.4,18.9 10.64,18.66 v1(19.92,18.66) 20.283,19.023 22.074,19.023 22.911,18.186 25.139,18.186 26.588,16.737 26.588,16.729 27.46,15.858 30.008,15.858 30.342,16.192 30.342,16.782 30.712,17.152 30.712,17.154 31.547,17.989 42.642,17.989 43.052,18.399 43.728,18.399 45.05,17.077 48.323,17.077 49.046,17.8 54.306,17.8 55.275,18.769 61.269,18.769 62.723,20.224 62.723,20.273 63.75,21.3 64.725,21.3 65.532,22.107 68.322,22.107 72.029,18.4 73,18.4 74.408,19.808 82.771,19.808 83.448,20.485 87.315,20.485 88.656,21.825 88.656,23.869 88.039,24.486 88.039,24.92 88.843,25.725 88.843,34.892 88.564,35.171 88.039,35.171 v1(87.14,36.07)
  Bottom w0.127: R233.1@17.255,19.125 17.255,18.545 17.625,18.175 19.435,18.175 v1(19.92,18.66)
CAN/RS485#: R163.1 U1.AG13 U4.6 U5.6 | length 39
  Top w0.127: v1(55.44,43.66) 55.44,43.65 U1.AG13@56.05,43.04
  Signal_4 w0.142: v1(24.5,43.325) 24.7,43.525 29.675,43.525 30.425,42.775 32.917,42.775 33.065,42.923 33.415,42.923 33.563,42.775 37.215,42.775 38.509,44.069 46.194,44.069 46.5,44.375 54.725,44.375 v1(55.44,43.66)
  Bottom w0.127: v1(24.5,43.325) 24.5,43.689 U4.6@24.636,43.825 ; U4.6@24.65,43.825 U4.6@24.636,43.825 ; U5.6@24.775,47.75 24.5,47.75 23.725,46.975 23.725,46.575 23.68,46.53 R163.1@23.68,46.45 23.68,44.501 24.096,44.085 24.115,44.085 24.375,43.825 U4.6@24.636,43.825
CONSOLE_RX: D6.2 J11.2 U1.V29 | length 69.2
  Top w0.127: v1(66.175,21.415) U1.V29@67.48,22.72
  Top w0.142: v1(96.55,53.35) D6.2@96.55,53.875
  Signal_3 w0.142: v1(66.175,21.415) 67.51,22.75 78.272,22.75 79.345,21.677 79.695,21.677 80.363,22.344 80.363,29.238 v1(80.85,29.725)
  Signal_8 w0.142: v1(80.85,29.725) 82.85,27.725 92.1,27.725 94.9,30.525 94.9,35.081 96.283,36.463 96.283,43.6 96.55,43.867 v1(96.55,53.35) 96.55,55.725 96.9,56.075 J11.2@96.9,57.475
CONSOLE_TX: D7.2 J11.1 U1.W29 | length 86.7
  Top w0.127: v1@60.828,16.909 62.022,16.909 62.297,17.185 62.297,19.325 65.692,22.72 U1.W29@66.21,22.72
  Top w0.142: D7.2@97.375,53.9 97.375,53.375 97.38,53.38 v1(97.38,53.502)
  Signal_8 w0.142: v1(60.675,16.975) 61.475,16.975 61.625,16.825 62.6,16.825 62.851,16.574 62.851,16.329 64.474,14.706 64.474,14.401 64.9,13.975 64.9,13.825 65.277,13.448 68.348,13.448 68.6,13.7 69.325,13.7 70.167,14.542 70.167,15.992 70.673,16.498 75.102,16.498 75.94,15.66 78.515,15.66 80.431,17.575 80.431,18.201 82.655,20.425 88,20.425 88.36,20.785 91.415,20.785 95.2,24.569 95.2,35 96.552,36.352 96.552,43.35 96.877,43.675 96.877,50.777 97.38,51.28 v1(97.38,53.502) 97.38,55.455 98.15,56.225 J11.1@98.15,57.475
CSI_D00: J17.2 U1.AH25 | length 94.2
  Top w0.127: v1(54.025,28.125) 54.362,28.125 54.687,27.8 U1.AH25@54.78,27.8
  Signal_3 w0.142: v1(9.75,67.5) 9.75,63.773 11.365,62.158 11.365,59.215 10.652,58.502 10.652,45.533 11.69,44.494 11.69,41.019 10.983,40.312 10.983,39.14 11.069,39.054 11.069,31.454 11.248,31.275 11.248,30.925 11.175,30.852 11.175,28.733 11.337,28.571 11.337,27.437 11.331,27.431 v1(11.21,27.431)
  Signal_4 w0.142: v1(11.21,27.431) 11.278,27.363 11.738,27.363 12.896,26.206 16.927,26.206 17.021,26.3 18.275,26.3 19,27.025 21.175,27.025 22.446,25.754 22.854,25.754 23.187,26.087 23.187,26.537 24,27.35 30.007,27.35 31.208,26.149 31.7,26.149 31.717,26.149 ccw(c31.717,26.303) 31.871,26.303 31.871,26.422 cw(c32.025,26.422) 32.025,26.576 32.059,26.576 cw(c32.059,26.422) 32.213,26.422 32.213,26.303 ccw(c32.367,26.303) 32.367,26.149 32.402,26.149 ccw(c32.402,26.303) 32.556,26.303 32.556,26.422 cw(c32.71,26.422) 32.71,26.576 32.744,26.576 cw(c32.744,26.422) 32.898,26.422 32.898,26.303 ccw(c33.052,26.303) 33.052,26.149 33.775,26.149 33.847,26.077 39.052,26.077 39.858,26.883 39.858,27.958 40.603,28.703 44.747,28.703 46.202,27.248 46.202,27.238 46.287,27.153 46.348,27.092 46.358,27.092 46.686,26.764 46.686,26.754 46.771,26.669 46.943,26.498 48.097,26.498 48.557,26.958 48.557,27.432 48.748,27.623 53.148,27.623 53.65,28.125 v1(54.025,28.125)
  Bottom w0.127: J17.2@9.75,66.65 v1(9.75,67.5)
CSI_D01: J17.3 U1.AH26 | length 93.2
  Top w0.127: v1(54.15,25.6) 54.78,26.23 U1.AH26@54.78,26.53
  Signal_3 w0.142: v1(10.25,68.1) 10.25,63.654 11.634,62.27 11.634,56.695 11.091,56.151 11.091,53.901 11.648,53.344 11.648,48.827 11.302,48.48 11.302,45.314 12.148,44.468 12.148,41.097 11.252,40.201 11.252,39.252 11.338,39.166 11.338,31.566 11.517,31.387 11.517,30.813 11.444,30.74 11.444,28.844 11.723,28.566 11.723,28.028 11.633,27.938 11.633,27.365 11.723,27.275 11.723,27.023 v1(11.3,26.6)
  Signal_4 w0.142: v1(11.3,26.6) 11.359,26.541 11.359,26.243 12.053,25.548 16.753,25.548 16.825,25.477 16.825,25.373 17.738,24.46 26.144,24.46 26.146,24.457 26.3,24.457 26.302,24.46 26.883,24.46 26.885,24.457 30.883,24.457 31.194,24.769 35.681,24.769 36.33,24.12 38.53,24.12 40.606,22.044 46.317,22.044 48.65,24.377 48.985,24.377 49.835,25.228 52.078,25.228 52.347,25.497 54.047,25.497 v1(54.15,25.6)
  Bottom w0.127: J17.3@10.25,66.65 v1(10.25,68.1)
CSI_D02: J17.4 U1.AJ25 | length 94.8
  Top w0.127: v1(52.65,27.2) 53.25,27.8 U1.AJ25@53.51,27.8
  Signal_3 w0.142: v1(10.75,67.5) 10.75,63.535 11.904,62.381 11.904,56.584 11.36,56.04 11.36,54.013 12.45,52.923 12.475,52.923 12.973,52.425 12.973,45.175 12.6,44.802 12.527,44.802 12.417,44.693 12.417,40.306 12.148,40.036 12.148,39.273 11.608,38.733 11.608,31.677 11.787,31.498 11.787,30.702 11.713,30.628 11.713,28.956 11.992,28.677 11.992,27.916 11.902,27.827 11.902,27.476 11.992,27.386 11.992,26.912 11.9,26.819 v1(11.9,26.3)
  Signal_4 w0.142: v1(11.9,26.3) 12.263,25.937 17.038,25.937 17.102,26 18.356,26 19.112,26.756 20.994,26.756 22.265,25.485 22.965,25.485 23.456,25.975 23.456,26.356 23.923,26.823 24.355,26.823 24.394,26.784 24.474,26.784 24.616,26.926 24.94,26.926 25.111,26.926 25.299,26.926 cw(c25.299,26.772) 25.453,26.772 25.453,26.56 ccw(c25.607,26.56) 25.607,26.406 25.641,26.406 ccw(c25.641,26.56) 25.795,26.56 25.795,26.772 cw(c25.949,26.772) 25.949,26.926 25.984,26.926 cw(c25.984,26.772) 26.138,26.772 26.138,26.556 ccw(c26.292,26.556) 26.292,26.402 26.326,26.402 ccw(c26.326,26.556) 26.48,26.556 26.48,26.772 cw(c26.634,26.772) 26.634,26.926 26.668,26.926 cw(c26.668,26.772) 26.822,26.772 26.822,26.54 ccw(c26.976,26.54) 26.976,26.386 27.01,26.386 ccw(c27.01,26.54) 27.164,26.54 27.164,26.772 cw(c27.318,26.772) 27.318,26.926 27.5,26.926 27.624,27.05 29.926,27.05 31.206,25.771 39.171,25.771 40.127,26.727 40.127,27.846 40.715,28.434 44.566,28.434 47.503,25.497 47.985,25.497 48.233,25.745 48.233,25.818 49.182,26.767 52.217,26.767 v1(52.65,27.2)
  Bottom w0.127: J17.4@10.75,66.65 v1(10.75,67.5)
CSI_D03: J17.5 U1.AH24 | length 92.8
  Top w0.127: v1(53.828,29.751) 53.899,29.751 54.58,29.07 U1.AH24@54.78,29.07
  Signal_3 w0.142: v1(11.25,68.1) 11.25,63.416 12.173,62.493 12.173,56.472 11.629,55.928 11.629,54.124 12.561,53.192 12.587,53.192 13.242,52.537 13.242,45.063 12.687,44.507 12.687,40.194 12.417,39.925 12.417,39.162 11.877,38.621 11.877,31.789 12.056,31.61 12.056,30.59 11.983,30.517 11.983,29.068 12.426,28.625 12.326,28.525 v1(12.326,27.651)
  Signal_4 w0.142: v1(12.326,27.651) 12.326,27.374 13.225,26.475 14.3,26.475 14.777,26.952 14.777,27.175 15.05,27.448 16.827,27.448 17.142,27.763 21.884,27.763 22.313,28.192 24.454,28.192 25.085,28.823 29.677,28.823 30.698,27.802 33.221,27.802 34.206,28.787 34.788,28.787 36.402,30.4 40.925,30.4 41.35,29.975 43,29.975 43.525,29.45 48.35,29.45 48.69,29.11 50.225,29.11 50.525,29.11 50.714,29.11 cw(c50.714,28.956) 50.868,28.956 50.868,28.527 ccw(c51.022,28.527) 51.022,28.373 51.056,28.373 ccw(c51.056,28.527) 51.21,28.527 51.21,28.956 cw(c51.364,28.956) 51.364,29.11 51.42,29.11 cw(c51.42,28.978) 51.552,28.978 ccw(c51.706,28.978) 51.706,28.824 51.74,28.824 ccw(c51.74,28.978) 51.894,28.978 cw(c52.026,28.978) 52.026,29.11 52.083,29.11 cw(c52.083,28.956) 52.237,28.956 ccw(c52.391,28.956) 52.391,28.802 52.425,28.802 ccw(c52.425,28.956) 52.579,28.956 cw(c52.733,28.956) 52.733,29.11 52.75,29.11 53.26,29.11 53.828,29.678 v1(53.828,29.751)
  Bottom w0.127: J17.5@11.25,66.65 v1(11.25,68.1)
CSI_D04: J17.6 U1.AJ23 | length 92.8
  Top w0.127: v1(52.89,29.73) 52.9,29.73 U1.AJ23@53.51,30.34
  Signal_3 w0.142: v1(11.75,67.5) 11.709,67.459 11.709,67.05 11.709,67.033 ccw(c11.863,67.033) 11.863,66.879 12.127,66.879 cw(c12.127,66.725) 12.281,66.725 12.281,66.691 cw(c12.127,66.691) 12.127,66.537 11.709,66.537 11.673,66.537 ccw(c11.673,66.383) 11.519,66.383 11.519,66.348 ccw(c11.673,66.348) 11.673,66.194 11.709,66.194 12.226,66.194 cw(c12.226,66.04) 12.38,66.04 12.38,66.006 cw(c12.226,66.006) 12.226,65.852 11.709,65.852 11.673,65.852 ccw(c11.673,65.698) 11.519,65.698 11.519,65.664 ccw(c11.673,65.664) 11.673,65.51 11.709,65.51 12.226,65.51 cw(c12.226,65.356) 12.38,65.356 12.38,65.322 cw(c12.226,65.322) 12.226,65.168 11.709,65.168 11.673,65.168 ccw(c11.673,65.014) 11.519,65.014 11.519,64.979 ccw(c11.673,64.979) 11.673,64.825 11.709,64.825 12.226,64.825 cw(c12.226,64.671) 12.38,64.671 12.38,64.637 cw(c12.226,64.637) 12.226,64.483 11.709,64.483 11.673,64.483 ccw(c11.673,64.329) 11.519,64.329 11.519,64.295 ccw(c11.673,64.295) 11.673,64.141 cw(c11.673,64.105) 11.709,64.105 11.709,63.875 11.709,63.338 12.442,62.604 12.442,56.361 11.898,55.817 11.898,54.236 12.673,53.462 12.698,53.462 13.623,52.537 13.623,44.625 13.623,44.454 13.623,44.266 cw(c13.469,44.266) 13.469,44.112 13.152,44.112 ccw(c13.152,43.958) 12.998,43.958 12.998,43.923 ccw(c13.152,43.923) 13.152,43.769 13.469,43.769 cw(c13.469,43.615) 13.623,43.615 13.623,43.581 cw(c13.469,43.581) 13.469,43.427 13.152,43.427 ccw(c13.152,43.273) 12.998,43.273 12.998,43.239 ccw(c13.152,43.239) 13.152,43.085 13.469,43.085 cw(c13.469,42.931) 13.623,42.931 13.623,42.75 13.623,40.75 12.687,39.813 12.687,39.037 12.277,38.627 12.277,35.851 12.723,35.405 12.723,32.818 12.325,32.42 12.325,30.479 12.252,30.405 12.252,29.544 13.494,28.301 v1(15.626,28.301)
  Signal_4 w0.142: v1(15.626,28.301) 15.626,28.082 15.594,28.05 15.716,27.928 16.926,27.928 17.03,28.033 21.773,28.033 22.202,28.462 24.342,28.462 24.973,29.092 34.714,29.092 36.446,30.825 45.25,30.825 45.525,31.1 47.127,31.1 47.475,30.752 47.475,30.75 47.825,30.4 52.22,30.4 v1(52.89,29.73)
  Bottom w0.127: J17.6@11.75,66.65 v1(11.75,67.5)
CSI_D05: J17.7 U1.AJ24 | length 95.4
  Top w0.127: v1(52.89,28.46) 52.9,28.46 U1.AJ24@53.51,29.07
  Signal_3 w0.142: v1(12.25,68.1) 12.25,67.2 12.67,66.78 12.67,64.016 12.59,63.935 12.59,63.426 12.52,63.357 12.52,62.955 12.711,62.764 12.711,56.249 12.168,55.705 12.168,54.347 12.784,53.731 12.81,53.731 13.892,52.648 13.892,40.55 13.28,39.938 13.28,36.921 12.944,36.585 12.944,35.565 12.992,35.517 12.992,33.046 13.323,32.716 13.323,31.75 13.323,31.696 12.827,31.2 12.827,30.723 13.098,30.452 13.098,29.078 13.577,28.6 15.025,28.6 15.15,28.725 15.801,28.725 16.049,28.477 16.049,28.126 15.801,27.878 15.505,27.878 15.225,27.598 v1(15.225,27.025)
  Signal_4 w0.142: v1(15.225,27.025) 15.698,26.552 16.892,26.552 16.94,26.6 18.163,26.6 18.963,27.4 22.176,27.4 22.499,27.077 23.202,27.077 23.85,27.725 30.013,27.725 30.692,27.046 33.608,27.046 34.113,27.551 34.45,27.551 34.621,27.551 34.809,27.551 cw(c34.809,27.397) 34.963,27.397 34.963,27.313 ccw(c35.117,27.313) 35.117,27.159 35.152,27.159 ccw(c35.152,27.313) 35.306,27.313 35.306,27.397 cw(c35.46,27.397) 35.46,27.551 35.494,27.551 cw(c35.494,27.397) 35.648,27.397 35.648,27.101 ccw(c35.802,27.101) 35.802,26.947 35.836,26.947 ccw(c35.836,27.101) 35.99,27.101 35.99,27.397 cw(c36.144,27.397) 36.144,27.551 36.175,27.551 36.376,27.551 38.075,29.25 39.75,29.25 40.15,29.65 42.875,29.65 43.344,29.181 45.111,29.181 46.217,28.075 46.229,28.063 ccw(c46.338,28.172) 46.447,28.063 46.641,28.257 cw(c46.75,28.148) 46.859,28.257 46.883,28.233 cw(c46.774,28.124) 46.883,28.015 46.58,27.712 46.469,27.601 ccw(c46.578,27.492) 46.469,27.383 46.493,27.359 ccw(c46.602,27.468) 46.711,27.359 46.822,27.47 47.118,27.766 cw(c47.227,27.657) 47.336,27.766 47.36,27.742 cw(c47.251,27.633) 47.36,27.524 47.064,27.228 46.953,27.117 ccw(c47.062,27.008) 46.953,26.899 46.977,26.875 ccw(c47.086,26.984) 47.195,26.875 47.197,26.877 cw(c47.306,26.768) 47.415,26.877 47.451,26.84 47.525,26.767 47.985,26.767 48.287,27.069 48.287,27.737 48.442,27.892 52.322,27.892 v1(52.89,28.46)
  Bottom w0.127: J17.7@12.25,66.65 v1(12.25,68.1)
CSI_D06: J17.8 U1.AH20 | length 91.6
  Top w0.127: v1(54.16,33.54) 54.17,33.54 U1.AH20@54.78,34.15
  Signal_3 w0.142: v1(12.75,67.5) 12.75,67.323 13.55,66.523 13.55,65.125 13.925,64.75 13.925,64.475 13.925,64.458 ccw(c14.079,64.458) 14.079,64.304 14.378,64.304 cw(c14.378,64.15) 14.532,64.15 14.532,64.116 cw(c14.378,64.116) 14.378,63.962 13.925,63.962 13.601,63.962 ccw(c13.601,63.808) 13.447,63.808 13.447,63.773 ccw(c13.601,63.773) 13.601,63.619 13.925,63.619 cw(c13.925,63.537) 14.007,63.537 14.007,63.359 cw(c13.925,63.359) 13.925,63.277 13.606,63.277 ccw(c13.606,63.123) 13.451,63.123 13.451,63.089 ccw(c13.606,63.089) 13.606,62.935 13.925,62.935 cw(c13.925,62.781) 14.079,62.781 14.079,62.747 cw(c13.925,62.747) 13.925,62.593 13.213,62.593 ccw(c13.213,62.439) 13.059,62.439 13.059,62.404 ccw(c13.213,62.404) 13.213,62.25 13.925,62.25 14.378,62.25 cw(c14.378,62.096) 14.532,62.096 14.532,62.062 cw(c14.378,62.062) 14.378,61.908 13.925,61.908 13.213,61.908 ccw(c13.213,61.754) 13.059,61.754 13.059,61.72 ccw(c13.213,61.72) 13.213,61.566 13.771,61.566 cw(c13.771,61.412) 13.925,61.412 13.925,61.225 13.925,60.875 13.925,60.858 ccw(c14.079,60.858) 14.079,60.704 cw(c14.079,60.55) 14.233,60.55 14.233,60.516 cw(c14.079,60.516) 14.079,60.362 13.925,60.362 13.665,60.362 ccw(c13.665,60.208) 13.511,60.208 13.511,60.173 ccw(c13.665,60.173) 13.665,60.019 13.806,60.019 cw(c13.806,59.9) 13.925,59.9 13.925,57.065 12.437,55.577 12.437,54.459 12.896,54 12.921,54 14.162,52.76 14.162,40.375 13.549,39.763 13.549,36.809 13.213,36.473 13.213,35.677 13.262,35.628 13.262,33.158 13.592,32.827 13.592,31.638 13.592,31.242 v1(13.3,30.95)
  Signal_4 w0.142: 13.275,30.7 13.427,30.548 14.774,30.548 14.825,30.6 15.176,30.6 15.251,30.525 15.579,30.525 15.601,30.503 21.844,30.503 22.59,31.25 26.581,31.25 27.274,31.943 34.17,31.943 34.627,32.4 42.85,32.4 44.125,33.675 46.361,33.675 46.6,33.913 52.427,33.913 52.462,33.878 53.702,33.878 54.04,33.54 v1(54.16,33.54)
  Bottom w0.127: J17.8@12.75,66.65 v1(12.75,67.5)
CSI_D07: J17.9 U1.AJ22 | length 104.2
  Top w0.127: v1(52.9,31.4) 53.3,31.4 U1.AJ22@53.51,31.61
  Signal_3 w0.142: v1(13.25,68.1) 13.25,67.375 13.9,66.725 13.9,65.48 15.725,63.655 15.725,62.705 15.511,62.491 15.511,61.745 15.511,61.574 15.511,61.386 cw(c15.357,61.386) 15.357,61.232 14.743,61.232 ccw(c14.743,61.078) 14.589,61.078 14.589,61.044 ccw(c14.743,61.044) 14.743,60.89 15.357,60.89 cw(c15.357,60.736) 15.511,60.736 15.511,60.701 cw(c15.357,60.701) 15.357,60.547 15.225,60.547 ccw(c15.225,60.393) 15.071,60.393 15.071,60.359 ccw(c15.225,60.359) 15.225,60.205 15.357,60.205 cw(c15.357,60.051) 15.511,60.051 15.511,60.017 cw(c15.357,60.017) 15.357,59.863 15.105,59.863 ccw(c15.105,59.709) 14.951,59.709 14.951,59.675 ccw(c15.105,59.675) 15.105,59.521 15.357,59.521 cw(c15.357,59.367) 15.511,59.367 15.511,59.333 cw(c15.357,59.333) 15.357,59.179 15.245,59.179 ccw(c15.245,59.025) 15.091,59.025 15.091,58.99 ccw(c15.245,58.99) 15.245,58.836 15.357,58.836 cw(c15.357,58.682) 15.511,58.682 15.511,58.648 cw(c15.357,58.648) 15.357,58.494 15.049,58.494 ccw(c15.049,58.34) 14.895,58.34 14.895,58.306 ccw(c15.049,58.306) 15.049,58.152 15.357,58.152 cw(c15.357,57.998) 15.511,57.998 15.511,57.964 cw(c15.357,57.964) 15.357,57.81 14.743,57.81 ccw(c14.743,57.656) 14.589,57.656 14.589,57.621 ccw(c14.743,57.621) 14.743,57.467 15.357,57.467 cw(c15.357,57.313) 15.511,57.313 15.511,57.125 15.511,57.025 15.511,56.886 14.834,56.209 14.834,55.228 14.923,55.138 14.923,53.57 14.431,53.078 14.431,40.263 13.818,39.651 13.818,36.698 13.483,36.362 13.483,35.788 13.531,35.74 13.531,33.269 13.862,32.939 13.862,31.527 13.862,30.906 13.678,30.722 13.678,29.722 14.25,29.15 v1(14.25,29.125)
  Signal_4 w0.142: v1(14.25,29.125) 13.902,28.777 12.398,28.777 11.775,29.4 11.775,32.869 11.781,32.875 11.781,32.9 14.204,35.323 14.975,35.323 15.093,35.206 15.6,35.206 16.219,35.825 22.569,35.825 23.617,34.777 30.802,34.777 31.008,34.983 34.638,34.983 35.031,35.375 35.275,35.375 36.425,36.525 39.05,36.525 40.368,37.843 46.195,37.843 46.263,37.775 48.625,37.775 v1(48.975,37.425)
  Signal_7 w0.142: v1(48.975,37.425) 48.975,36.225 52.2,33 52.2,32.1 v1(52.9,31.4)
  Bottom w0.127: J17.9@13.25,66.65 v1(13.25,68.1)
CSI_EN: J17.15 U1.AK27 | length 93.2
  Top w0.127: v1(51.62,24.65) 51.63,24.65 U1.AK27@52.24,25.26
  Signal_3 w0.142: v1(16.25,68.1) 16.25,66.075 17.8,64.525 17.8,56.924 17.885,56.84 17.885,53.938 16.5,52.554 16.5,48.825 16.7,48.625 16.712,48.613 ccw(c16.821,48.722) 16.93,48.613 17.137,48.82 cw(c17.246,48.712) 17.355,48.82 17.379,48.796 cw(c17.271,48.687) 17.379,48.578 17.063,48.262 16.562,47.761 ccw(c16.67,47.652) 16.562,47.543 16.586,47.519 ccw(c16.695,47.627) 16.804,47.519 17.196,47.911 cw(c17.305,47.802) 17.414,47.911 17.547,47.778 17.704,47.621 17.704,47.45 17.704,47.262 ccw(c17.858,47.262) 17.858,47.108 18.382,47.108 cw(c18.382,46.954) 18.536,46.954 18.536,46.92 cw(c18.382,46.92) 18.382,46.766 17.704,46.766 16.832,46.766 ccw(c16.832,46.612) 16.678,46.612 16.678,46.577 ccw(c16.832,46.577) 16.832,46.423 17.631,46.423 cw(c17.631,46.35) 17.704,46.35 17.704,45.704 17.548,45.548 17.548,39.95 16.851,39.253 16.851,36.431 15.644,35.224 15.644,34.494 15.103,33.952 15.103,33.601 15.225,33.479 15.225,32.975 17.174,31.026 17.174,28.024 16.55,27.4 16.55,25.05 v1(16.5,25)
  Signal_4 w0.142: v1(16.5,25) 16.538,25 17.35,24.188 31.15,24.188 31.461,24.499 35.57,24.499 36.218,23.851 38.399,23.851 40.475,21.775 47.673,21.775 50.008,24.11 51.08,24.11 v1(51.62,24.65)
  Bottom w0.127: J17.15@16.25,66.65 v1(16.25,68.1)
CSI_HSYNC: J17.13 U1.AK28 | length 94.1
  Top w0.127: v1(51.62,23.38) 51.63,23.38 U1.AK28@52.24,23.99
  Signal_3 w0.142: v1(15.25,68.1) 15.25,66.25 17.15,64.35 17.15,56.676 17.346,56.48 17.346,54.161 15.26,52.075 15.26,40.325 16.313,39.273 16.313,36.654 14.982,35.323 14.625,35.323 14.339,35.037 14.339,34.161 14.564,33.936 14.564,33.378 14.675,33.268 14.675,31.24 15.424,30.492 15.424,29.948 15.078,29.602 15.078,29.251 15.335,28.994 15.913,28.994 16.318,28.588 16.318,28.015 15.648,27.345 15.648,25.798 15.275,25.425 15.301,25.399 v1(15.301,25.026)
  Signal_4 w0.142: v1(15.301,25.026) 14.51,25.026 14.484,25 14.2,24.716 14.2,23.95 14.324,23.826 14.8,23.826 14.817,23.826 ccw(c14.817,23.98) 14.971,23.98 14.971,24.257 cw(c15.125,24.257) 15.125,24.411 15.159,24.411 cw(c15.159,24.257) 15.313,24.257 15.313,23.98 ccw(c15.467,23.98) 15.467,23.826 15.502,23.826 ccw(c15.502,23.98) 15.656,23.98 15.656,24.23 cw(c15.81,24.23) 15.81,24.384 15.844,24.384 cw(c15.844,24.23) 15.998,24.23 15.998,23.98 ccw(c16.152,23.98) 16.152,23.826 16.225,23.826 34.25,23.826 34.516,23.56 38.29,23.56 40.5,21.35 44.302,21.35 44.925,20.727 45.291,20.727 ; 45.292,20.727 45.527,20.727 46.25,21.45 47.729,21.45 48.954,22.675 50.915,22.675 v1(51.62,23.38)
  Bottom w0.127: J17.13@15.25,66.65 v1(15.25,68.1)
CSI_MCLK: J17.11 U1.AJ21 | length 91.6
  Top w0.127: v1(52.89,32.27) 52.9,32.27 U1.AJ21@53.51,32.88
  Signal_3 w0.142: v1(14.101,29.976) 14.111,29.976 14.131,29.996 14.131,31.415 14.131,33.05 13.8,33.381 13.8,35.852 13.752,35.9 13.752,36.25 14.088,36.586 14.088,39.516 14.722,40.15 14.722,52.299 16.808,54.384 16.808,56.167 15.828,57.147 15.828,57.712 15.85,57.734 15.85,58.068 15.828,58.09 15.828,58.396 15.85,58.418 15.85,58.752 15.828,58.775 15.828,59.081 15.85,59.103 15.85,59.437 15.828,59.459 15.828,59.765 15.85,59.787 15.85,60.121 15.828,60.143 15.828,60.45 15.85,60.472 15.85,60.806 15.828,60.828 15.828,61.134 15.85,61.156 15.85,61.49 15.828,61.512 15.828,61.819 15.85,61.841 15.85,62 16.6,62.75 16.6,64.094 14.25,66.444 v1(14.25,68.1)
  Signal_4 w0.142: v1(14.101,29.976) 14.5,29.976 14.775,29.702 15.125,29.702 15.388,29.965 22.115,29.965 22.798,30.648 27.828,30.648 28.025,30.845 28.042,30.845 ccw(c28.042,30.999) 28.196,30.999 28.196,31.141 cw(c28.35,31.141) 28.35,31.295 28.384,31.295 cw(c28.384,31.141) 28.538,31.141 28.538,30.999 ccw(c28.692,30.999) 28.692,30.845 28.881,30.845 29.025,30.845 29.8,30.845 29.877,30.845 ccw(c29.877,30.999) 30.031,30.999 30.031,31.148 cw(c30.185,31.148) 30.185,31.302 30.22,31.302 cw(c30.22,31.148) 30.374,31.148 30.374,30.999 ccw(c30.528,30.999) 30.528,30.845 30.562,30.845 ccw(c30.562,30.999) 30.716,30.999 30.716,31.148 cw(c30.87,31.148) 30.87,31.302 30.904,31.302 cw(c30.904,31.148) 31.058,31.148 31.058,30.999 ccw(c31.212,30.999) 31.212,30.845 31.246,30.845 ccw(c31.246,30.999) 31.4,30.999 31.4,31.148 cw(c31.554,31.148) 31.554,31.302 31.589,31.302 cw(c31.589,31.148) 31.743,31.148 31.743,30.999 ccw(c31.897,30.999) 31.897,30.845 31.931,30.845 ccw(c31.931,30.999) 32.085,30.999 32.085,31.148 cw(c32.239,31.148) 32.239,31.302 32.273,31.302 cw(c32.273,31.148) 32.427,31.148 32.427,30.999 ccw(c32.581,30.999) 32.581,30.845 32.615,30.845 ccw(c32.615,30.999) 32.769,30.999 32.769,31.148 cw(c32.923,31.148) 32.923,31.302 32.958,31.302 cw(c32.958,31.148) 33.112,31.148 33.112,30.999 ccw(c33.266,30.999) 33.266,30.845 33.454,30.845 33.625,30.845 33.833,30.845 34.713,31.725 43.1,31.725 43.81,32.435 46.491,32.435 47.431,33.375 48.075,33.375 48.131,33.375 48.32,33.375 cw(c48.32,33.221) 48.474,33.221 48.474,33.04 ccw(c48.628,33.04) 48.628,32.886 48.662,32.886 ccw(c48.662,33.04) 48.816,33.04 48.816,33.221 cw(c48.97,33.221) 48.97,33.375 49.004,33.375 cw(c49.004,33.221) 49.158,33.221 49.158,33.116 ccw(c49.312,33.116) 49.312,32.962 49.346,32.962 ccw(c49.346,33.116) 49.5,33.116 49.5,33.221 cw(c49.654,33.221) 49.654,33.375 49.689,33.375 cw(c49.689,33.221) 49.843,33.221 49.843,33.116 ccw(c49.997,33.116) 49.997,32.962 50.031,32.962 ccw(c50.031,33.116) 50.185,33.116 50.185,33.221 cw(c50.339,33.221) 50.339,33.375 50.373,33.375 cw(c50.373,33.221) 50.527,33.221 50.527,33.116 ccw(c50.681,33.116) 50.681,32.962 50.715,32.962 ccw(c50.715,33.116) 50.869,33.116 50.869,33.221 cw(c51.023,33.221) 51.023,33.375 51.058,33.375 cw(c51.058,33.221) 51.212,33.221 51.212,33.116 ccw(c51.366,33.116) 51.366,32.962 51.4,32.962 ccw(c51.4,33.116) 51.554,33.116 51.554,33.221 cw(c51.708,33.221) 51.708,33.375 51.725,33.375 52.15,33.375 52.89,32.635 v1(52.89,32.27)
  Bottom w0.127: J17.11@14.25,66.65 v1(14.25,68.1)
